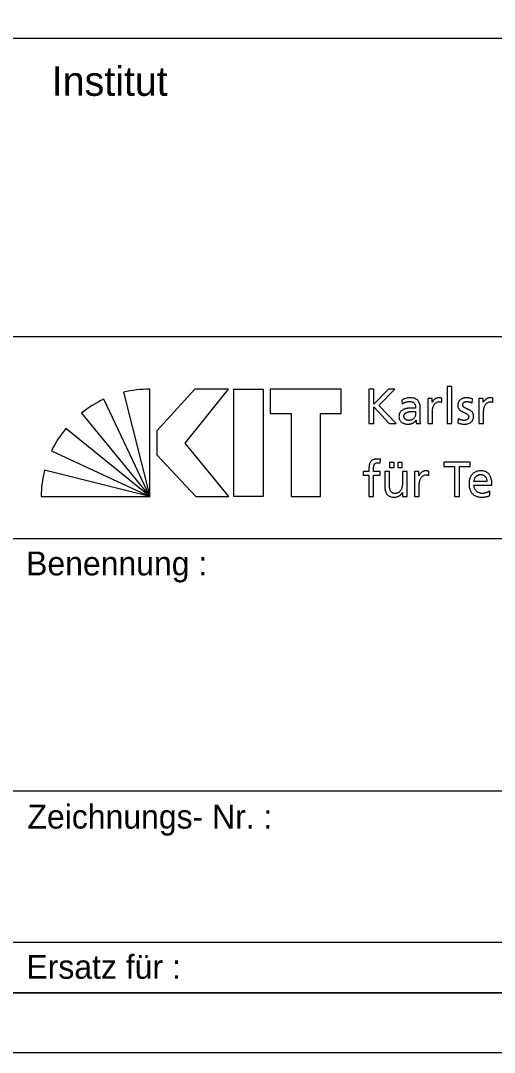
# Model space of a CAD drawing. Extents: x 0 to 420, y 0 to 297.
# Drawn here: x 376.33 to 396.16, y 0 to 43.24 of the extents above; entities that cross this region are included whole.
import ezdxf

# ---------------------------------------------------------------- set-up
doc = ezdxf.new("R2010")
doc.units = 0
doc.layers.add('90_Plankopf', color=7, linetype='Continuous')

msp = doc.modelspace()

# ---------------------------------------------------------------- linework, layer by layer
at = {"layer": '90_Plankopf'}
for p, q in [((418, 42.495), (329.06, 42.495)), ((329.06, 29.995), (418, 29.995)), ((329.06, 29.995), (418, 29.995)), ((381.74, 23.293), (381.74, 27.792)), ((390.905, 27.793), (390.905, 26.353)), ((381.74, 23.293), (379.817, 27.376)), ((380.637, 27.666), (381.74, 23.293)), ((392.29, 27.331), (392.3, 27.166)), ((393.963, 27.242), (393.963, 27.416)), ((395.228, 27.22), (395.245, 27.389)), ((396.106, 27.242), (396.106, 27.416)), ((392.865, 26.854), (392.865, 26.761)), ((393.059, 26.559), (393.059, 26.995)), ((378.872, 26.793), (381.74, 23.293)), ((394.649, 26.559), (394.638, 26.386)), ((381.74, 23.293), (378.217, 26.143)), ((390.905, 26.353), (391.111, 26.353)), ((391.753, 26.353), (392.054, 26.353)), ((377.62, 25.207), (381.74, 23.293)), ((391.387, 24.696), (391.395, 24.853)), ((381.74, 23.293), (377.329, 24.394)), ((393.413, 24.182), (393.413, 24.356)), ((395.853, 23.92), (395.308, 23.92)), ((395.308, 23.776), (396.059, 23.776)), ((395.979, 23.337), (395.979, 23.53)), ((377.182, 23.293), (381.74, 23.293)), ((376.001, 21.535), (418, 21.535)), ((376.001, 10.96), (418, 10.96)), ((376.001, 4.615), (418, 4.615)), ((418, 2.5), (329.06, 2.5)), ((334.9, 2.5), (418, 2.5)), ((334.9, 2.5), (418, 2.5))]:
    msp.add_line(p, q, dxfattribs=at)
for points in [[(0, 0), (420.5, 0), (420.5, 297), (0, 297)], [(12.5, 294.5), (418, 294.5), (418, 2.5), (12.5, 2.5)], [(385.033, 27.793), (383.618, 27.793), (382.036, 26.049), (382.036, 25.046), (383.669, 23.293), (385.042, 23.293), (383.211, 25.531)], [(386.485, 27.793), (386.485, 23.293), (385.251, 23.293), (385.251, 27.793)], [(386.781, 27.793), (386.781, 26.78), (387.651, 26.78), (387.651, 23.293), (388.885, 23.293), (388.885, 26.78), (389.755, 26.78), (389.755, 27.793)]]:
    msp.add_lwpolyline(points, close=True, dxfattribs=at)
for points in [[(392.054, 26.353), (391.324, 27.112), (392, 27.793), (391.726, 27.793), (391.111, 27.16), (391.111, 27.793), (390.905, 27.793)], [(394.19, 26.353), (394.384, 26.353), (394.384, 27.9), (394.19, 27.9), (394.19, 26.353)], [(393.561, 27.242), (393.557, 27.242), (393.557, 27.405), (393.375, 27.405), (393.375, 26.353), (393.569, 26.353), (393.569, 26.832)], [(395.703, 27.242), (395.699, 27.242), (395.699, 27.405), (395.518, 27.405), (395.518, 26.353), (395.712, 26.353), (395.712, 26.832)], [(391.111, 26.353), (391.111, 27.059), (391.753, 26.353)], [(392.882, 26.489), (392.886, 26.489), (392.886, 26.353), (393.067, 26.353)], [(391.777, 24.713), (391.777, 24.506), (391.971, 24.506), (391.971, 24.713), (391.777, 24.713)], [(392.115, 24.713), (392.115, 24.506), (392.309, 24.506), (392.309, 24.713), (392.115, 24.713)], [(394.495, 23.293), (394.701, 23.293), (394.701, 24.552), (395.149, 24.552), (395.149, 24.733), (394.047, 24.733), (394.047, 24.552), (394.495, 24.552), (394.495, 23.293)], [(390.912, 24.443), (390.912, 24.346), (390.665, 24.346), (390.665, 24.189), (390.912, 24.189), (390.912, 23.293), (391.106, 23.293), (391.106, 24.189), (391.385, 24.189), (391.385, 24.346), (391.106, 24.346), (391.106, 24.459)], [(391.771, 23.801), (391.771, 24.346), (391.577, 24.346), (391.577, 23.72)], [(392.507, 23.293), (392.507, 24.346), (392.313, 24.346), (392.313, 23.859)], [(393.011, 24.182), (393.007, 24.182), (393.007, 24.346), (392.825, 24.346), (392.825, 23.293), (393.019, 23.293), (393.019, 23.772)], [(392.316, 23.46), (392.32, 23.46), (392.32, 23.293), (392.507, 23.293)]]:
    msp.add_lwpolyline(points, dxfattribs=at)
for centre, start, end in [((381.724, 23.028), 89.8053, 103.1895), ((381.831, 23.059), 115.0126, 128.3968), ((381.908, 23.131), 140.7898, 154.174), ((381.946, 23.219), 165.7222, 179.1064)]:
    msp.add_arc(centre, 4.764, start, end, dxfattribs=at)
for points in [[(393.059, 26.995), (393.06, 27.09), (393.045, 27.17), (393.017, 27.235), (392.988, 27.3), (392.942, 27.348), (392.88, 27.381), (392.817, 27.413), (392.736, 27.43), (392.636, 27.43), (392.569, 27.43), (392.507, 27.42), (392.449, 27.402), (392.391, 27.384), (392.338, 27.361), (392.29, 27.331)], [(392.3, 27.166), (392.326, 27.188), (392.356, 27.207), (392.39, 27.223), (392.423, 27.239), (392.458, 27.251), (392.495, 27.26), (392.532, 27.269), (392.568, 27.273), (392.605, 27.273), (392.67, 27.273), (392.721, 27.263), (392.759, 27.243), (392.797, 27.222), (392.824, 27.191), (392.841, 27.151), (392.858, 27.11), (392.865, 27.059), (392.865, 26.999)], [(393.963, 27.416), (393.95, 27.418), (393.937, 27.421), (393.925, 27.423), (393.912, 27.425), (393.899, 27.427), (393.885, 27.428), (393.871, 27.429), (393.854, 27.43), (393.835, 27.43), (393.798, 27.43), (393.761, 27.422), (393.726, 27.406), (393.691, 27.39), (393.659, 27.368), (393.63, 27.339), (393.601, 27.311), (393.578, 27.279), (393.561, 27.242)], [(393.569, 26.832), (393.569, 26.92), (393.581, 26.996), (393.605, 27.06), (393.629, 27.124), (393.662, 27.174), (393.705, 27.208), (393.747, 27.243), (393.798, 27.26), (393.856, 27.261), (393.873, 27.261), (393.89, 27.26), (393.909, 27.257), (393.927, 27.254), (393.945, 27.249), (393.963, 27.242)], [(395.245, 27.389), (395.207, 27.4), (395.169, 27.41), (395.13, 27.418), (395.091, 27.426), (395.049, 27.43), (395.004, 27.43), (394.951, 27.43), (394.903, 27.423), (394.858, 27.41), (394.813, 27.397), (394.774, 27.377), (394.74, 27.35), (394.706, 27.323), (394.68, 27.29), (394.661, 27.249), (394.642, 27.208), (394.632, 27.161), (394.632, 27.106), (394.632, 27.064), (394.641, 27.028), (394.658, 26.997), (394.674, 26.966), (394.695, 26.94), (394.723, 26.917), (394.75, 26.895), (394.779, 26.875), (394.812, 26.857), (394.844, 26.84), (394.876, 26.824), (394.909, 26.809), (394.941, 26.793), (394.971, 26.777), (394.998, 26.761), (395.025, 26.745), (395.047, 26.727), (395.063, 26.706), (395.079, 26.686), (395.088, 26.663), (395.088, 26.636), (395.088, 26.607), (395.082, 26.584), (395.07, 26.564), (395.058, 26.545), (395.042, 26.529), (395.022, 26.518), (395.003, 26.506), (394.982, 26.498), (394.959, 26.493), (394.935, 26.487), (394.912, 26.485), (394.89, 26.485), (394.871, 26.485), (394.847, 26.488), (394.82, 26.493), (394.792, 26.499), (394.763, 26.507), (394.733, 26.518), (394.703, 26.529), (394.675, 26.543), (394.649, 26.559)], [(394.638, 26.386), (394.683, 26.363), (394.73, 26.347), (394.779, 26.339), (394.828, 26.331), (394.877, 26.327), (394.927, 26.328), (394.975, 26.328), (395.02, 26.335), (395.064, 26.348), (395.107, 26.361), (395.147, 26.381), (395.181, 26.408), (395.216, 26.435), (395.243, 26.469), (395.264, 26.51), (395.284, 26.551), (395.294, 26.6), (395.295, 26.656), (395.294, 26.704), (395.286, 26.745), (395.269, 26.778), (395.253, 26.811), (395.231, 26.84), (395.204, 26.863), (395.177, 26.886), (395.147, 26.906), (395.115, 26.922), (395.083, 26.939), (395.05, 26.954), (395.018, 26.968), (394.986, 26.983), (394.956, 26.998), (394.929, 27.013), (394.902, 27.029), (394.88, 27.047), (394.864, 27.068), (394.847, 27.089), (394.839, 27.115), (394.838, 27.145), (394.839, 27.174), (394.848, 27.198), (394.865, 27.217), (394.882, 27.236), (394.904, 27.25), (394.932, 27.259), (394.96, 27.269), (394.991, 27.273), (395.024, 27.273), (395.036, 27.273), (395.051, 27.271), (395.069, 27.269), (395.088, 27.266), (395.107, 27.261), (395.127, 27.256), (395.148, 27.251), (395.167, 27.246), (395.185, 27.239), (395.203, 27.233), (395.217, 27.226), (395.228, 27.22)], [(396.106, 27.416), (396.092, 27.418), (396.079, 27.421), (396.067, 27.423), (396.055, 27.425), (396.041, 27.427), (396.027, 27.428), (396.013, 27.429), (395.997, 27.43), (395.978, 27.43), (395.94, 27.43), (395.904, 27.422), (395.868, 27.406), (395.833, 27.39), (395.801, 27.368), (395.773, 27.339), (395.744, 27.311), (395.721, 27.279), (395.703, 27.242)], [(395.712, 26.832), (395.712, 26.92), (395.724, 26.996), (395.747, 27.06), (395.771, 27.124), (395.804, 27.174), (395.847, 27.208), (395.89, 27.243), (395.94, 27.26), (395.998, 27.261), (396.015, 27.261), (396.033, 27.26), (396.051, 27.257), (396.07, 27.254), (396.088, 27.249), (396.106, 27.242)], [(392.865, 26.999), (392.84, 27), (392.817, 27.001), (392.795, 27.001), (392.773, 27.002), (392.751, 27.003), (392.729, 27.003), (392.708, 27.003), (392.684, 27.003), (392.659, 27.003), (392.618, 27.003), (392.576, 26.999), (392.531, 26.992), (392.487, 26.985), (392.443, 26.973), (392.4, 26.957), (392.358, 26.941), (392.319, 26.919), (392.284, 26.892), (392.25, 26.866), (392.222, 26.833), (392.201, 26.794), (392.181, 26.755), (392.171, 26.709), (392.17, 26.656), (392.171, 26.58), (392.187, 26.518), (392.219, 26.469), (392.252, 26.421), (392.297, 26.385), (392.355, 26.362), (392.413, 26.339), (392.479, 26.328), (392.556, 26.328), (392.6, 26.328), (392.64, 26.334), (392.675, 26.344), (392.71, 26.355), (392.741, 26.368), (392.768, 26.384), (392.795, 26.401), (392.818, 26.419), (392.837, 26.437), (392.855, 26.455), (392.87, 26.472), (392.882, 26.489)], [(392.865, 26.761), (392.865, 26.709), (392.854, 26.661), (392.832, 26.62), (392.81, 26.578), (392.777, 26.546), (392.733, 26.522), (392.69, 26.498), (392.636, 26.485), (392.572, 26.485), (392.55, 26.485), (392.527, 26.489), (392.504, 26.496), (392.481, 26.503), (392.46, 26.514), (392.441, 26.529), (392.422, 26.543), (392.406, 26.561), (392.394, 26.582), (392.383, 26.604), (392.377, 26.628), (392.376, 26.656), (392.377, 26.693), (392.386, 26.724), (392.404, 26.749), (392.422, 26.773), (392.446, 26.793), (392.475, 26.807), (392.503, 26.822), (392.534, 26.833), (392.567, 26.841), (392.6, 26.848), (392.632, 26.853), (392.663, 26.855), (392.694, 26.858), (392.72, 26.859), (392.741, 26.858), (392.762, 26.858), (392.783, 26.858), (392.803, 26.856), (392.824, 26.855), (392.845, 26.855), (392.865, 26.854)], [(393.067, 26.353), (393.066, 26.363), (393.065, 26.377), (393.063, 26.393), (393.062, 26.411), (393.061, 26.433), (393.061, 26.46), (393.06, 26.486), (393.059, 26.52), (393.059, 26.559)], [(391.395, 24.853), (391.375, 24.856), (391.355, 24.859), (391.334, 24.862), (391.312, 24.864), (391.29, 24.866), (391.265, 24.866), (391.194, 24.865), (391.135, 24.855), (391.089, 24.836), (391.043, 24.816), (391.007, 24.787), (390.981, 24.75), (390.955, 24.713), (390.937, 24.668), (390.927, 24.616), (390.917, 24.565), (390.912, 24.507), (390.912, 24.443)], [(391.106, 24.459), (391.106, 24.495), (391.108, 24.528), (391.112, 24.558), (391.116, 24.588), (391.125, 24.615), (391.137, 24.637), (391.15, 24.66), (391.169, 24.677), (391.194, 24.69), (391.219, 24.702), (391.252, 24.709), (391.294, 24.709), (391.311, 24.709), (391.328, 24.708), (391.344, 24.706), (391.361, 24.703), (391.375, 24.7), (391.387, 24.696)], [(393.413, 24.356), (393.4, 24.359), (393.387, 24.361), (393.375, 24.363), (393.363, 24.365), (393.349, 24.367), (393.335, 24.368), (393.321, 24.37), (393.304, 24.37), (393.286, 24.37), (393.248, 24.37), (393.212, 24.362), (393.176, 24.346), (393.141, 24.33), (393.109, 24.308), (393.081, 24.28), (393.052, 24.252), (393.029, 24.219), (393.011, 24.182)], [(396.059, 23.776), (396.06, 23.861), (396.052, 23.94), (396.036, 24.012), (396.02, 24.084), (395.995, 24.146), (395.959, 24.2), (395.923, 24.254), (395.875, 24.295), (395.815, 24.325), (395.756, 24.355), (395.682, 24.37), (395.595, 24.37), (395.52, 24.37), (395.453, 24.357), (395.392, 24.331), (395.332, 24.305), (395.28, 24.269), (395.237, 24.221), (395.194, 24.174), (395.16, 24.118), (395.137, 24.052), (395.114, 23.988), (395.102, 23.916), (395.102, 23.838), (395.102, 23.752), (395.113, 23.674), (395.134, 23.604), (395.156, 23.535), (395.19, 23.475), (395.234, 23.425), (395.279, 23.375), (395.335, 23.336), (395.404, 23.309), (395.473, 23.282), (395.553, 23.269), (395.647, 23.268), (395.704, 23.269), (395.753, 23.273), (395.793, 23.28), (395.834, 23.288), (395.869, 23.297), (395.898, 23.307), (395.928, 23.317), (395.954, 23.327), (395.979, 23.337)], [(395.308, 23.92), (395.312, 23.955), (395.32, 23.989), (395.332, 24.024), (395.344, 24.058), (395.361, 24.089), (395.384, 24.118), (395.406, 24.147), (395.434, 24.17), (395.469, 24.187), (395.503, 24.204), (395.543, 24.213), (395.591, 24.213), (395.633, 24.213), (395.67, 24.206), (395.702, 24.19), (395.735, 24.175), (395.762, 24.154), (395.785, 24.127), (395.807, 24.101), (395.824, 24.069), (395.835, 24.034), (395.847, 23.999), (395.853, 23.961), (395.853, 23.92)], [(392.313, 23.859), (392.313, 23.794), (392.307, 23.736), (392.295, 23.683), (392.282, 23.63), (392.263, 23.584), (392.236, 23.546), (392.21, 23.507), (392.177, 23.478), (392.137, 23.457), (392.096, 23.436), (392.049, 23.426), (391.994, 23.425), (391.938, 23.429), (391.893, 23.444), (391.861, 23.473), (391.828, 23.501), (391.805, 23.542), (391.791, 23.597), (391.777, 23.651), (391.771, 23.719), (391.771, 23.801)], [(393.019, 23.772), (393.02, 23.86), (393.032, 23.937), (393.055, 24.001), (393.079, 24.065), (393.112, 24.114), (393.155, 24.148), (393.198, 24.183), (393.248, 24.201), (393.306, 24.201), (393.323, 24.201), (393.341, 24.2), (393.359, 24.197), (393.378, 24.195), (393.396, 24.19), (393.413, 24.182)], [(391.577, 23.72), (391.577, 23.626), (391.591, 23.545), (391.618, 23.478), (391.646, 23.41), (391.69, 23.359), (391.748, 23.323), (391.806, 23.287), (391.88, 23.269), (391.971, 23.268), (392.02, 23.269), (392.068, 23.276), (392.113, 23.291), (392.158, 23.307), (392.198, 23.329), (392.233, 23.357), (392.268, 23.386), (392.296, 23.42), (392.316, 23.46)], [(395.979, 23.53), (395.967, 23.521), (395.949, 23.51), (395.926, 23.497), (395.903, 23.485), (395.877, 23.474), (395.847, 23.463), (395.817, 23.452), (395.786, 23.443), (395.753, 23.436), (395.72, 23.429), (395.687, 23.426), (395.655, 23.425), (395.608, 23.426), (395.565, 23.434), (395.523, 23.451), (395.482, 23.468), (395.445, 23.492), (395.413, 23.523), (395.38, 23.554), (395.355, 23.59), (395.336, 23.633), (395.318, 23.676), (395.309, 23.724), (395.308, 23.776)]]:
    msp.add_open_spline(points, degree=3, dxfattribs=at)

# ---------------------------------------------------------------- texts
for s, height, p in [('Institut', 1.232, (377.632, 40.087)), ('Benennung :', 1, (376.557, 19.989)), ('Zeichnungs- Nr. :', 1, (376.614, 9.379)), ('Ersatz für :', 1, (376.569, 3.084))]:
    msp.add_text(s, height=height, dxfattribs=at).set_placement(p)

doc.saveas('drawing.dxf')
